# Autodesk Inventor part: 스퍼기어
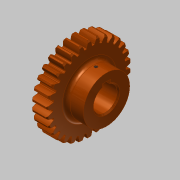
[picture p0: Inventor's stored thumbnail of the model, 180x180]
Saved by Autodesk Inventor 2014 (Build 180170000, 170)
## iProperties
Created: 2019-01
Part Number: 스퍼기어
Material: 알루미늄 6061
Document SubType Name: Modeling
Designer: mduedu
Density: 1 g/cm^3
Appearance: 매끄러움 - 연한 주황색
Author: mduedu
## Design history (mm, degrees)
sketch "스케치1"
  geometry: C1 r 27.5 at (0, 0); 1 further point
  constraints: 1 centre point, 1 coincident
  dimensions: "d0" = 55 diameter of C1
extrude "돌출1" new body sketch "스케치1" stored distance "d2" = 12; taper "d3" = 0 deg
sketch "스케치2" dims "d4" = 60
  geometry: L1 (0, 0)-(-32, 0); L2 (0, 0)-(0, 32); L3 (-0.57, 0)-(-0.57, 31.995); L4 (-1.57, 0)-(-1.57, 31.961); L5 (-2.07, 0)-(-2.07, 31.933); C1 r 27.5 at (0, 0); A1 r 32 centre (0, 0) between (-32, 0) and (0, 32); A2 r 9.292 centre (7.208, 26.911) between (-0.57, 31.995) and (-2.07, 27.422); A3 r 9.292 centre (-7.208, 26.911) between (2.07, 27.422) and (0.57, 31.995); A4 r 27.5 centre (0, 0) between (2.07, 27.422) and (-2.07, 27.422); A5 r 32 centre (0, 0) between (0.57, 31.995) and (-0.57, 31.995); 3 further points
  constraints: 14 point on circle, 10 end point, 6 centre point, 5 coincident, 5 point on line, 3 symmetric about line, 2 parallel, 2 perpendicular, 1 horizontal, 7 other
  dimensions: "d6" = 64 diameter of A1; "d7" = 0.5 distance between parallel lines of L4 L5; "d8" = 1 distance between parallel lines of L3 L4; "d9" = 1.57 distance between parallel lines of L2 L4
extrude "돌출2" join sketch "스케치2" stored distance "d10" = 0; taper "d11" = 0 deg
chamfer "모따기1" distance "d12" = 1; stored, may be unused: second distance "d13" = 2, angle "d14" = 45 deg
fillet "모깎기1" dims "d15" = 0.5
sketch "스케치3"
  geometry: C1 r 17.5 at (0, 0); 1 further point
  constraints: 1 centre point, 1 coincident
  dimensions: "d19" = 35 diameter of C1
extrude "돌출3" join sketch "스케치3" distance "d20" = 13; taper "d21" = 0 deg
sketch "스케치4"
  geometry: L1 (-3, 8.485)-(3, 8.485); L2 (3, 8.485)-(3, 11.8); L3 (3, 11.8)-(-3, 11.8); L4 (-3, 11.8)-(-3, 8.485); A1 r 9 centre (0, 0) between (-3, 8.485) and (3, 8.485); 1 further point
  constraints: 8 end point, 2 parallel, 2 point on circle, 1 centre point, 1 coincident, 1 horizontal, 1 perpendicular
  dimensions: "d22" = 18 diameter of A1; "d23" = 6 distance of L2.end L3.end; "d24" = 20.8 dimension on A1 L3
extrude "돌출4" cut sketch "스케치4" stored distance "d25" = 13; taper "d26" = 0 deg
sketch "스케치5"
  geometry: C1 r 15 at (0, 0); C2 r 22.5 at (0, 0); 1 further point
  constraints: 2 centre point, 2 coincident
  dimensions: "d33" = 30 diameter of C1; "d34" = 45 diameter of C2
extrude "돌출5" cut sketch "스케치5" distance "d30" = 6; taper "d31" = 0 deg
fillet "모깎기2" dims "d32" = 3
node "작업 평면1"
sketch "스케치6"
  geometry: L1 (17.5, 13)-(-17.5, 13) reference; 2 further points
  constraints: 1 vertical alignment
  dimensions: "d35" = 8 distance from line of point (0, 5) L1
hole "구멍1" sketch "스케치6" at (0, 5) diameter "d36" = 2.459; stored, may be unused: countersink angle "d40" = 90 deg, drill point angle "d42" = 118 deg; dims "d37" = 6, "d38" = 4, "d39" = 2, "d41" = 8
fillet "모깎기3" dims "d43" = 3
chamfer "모따기2" distance "d44" = 1; stored, may be unused: second distance "d45" = 2, angle "d46" = 45 deg
node "솔리드1"
pattern_circular "원형 패턴1" dims "d17" = 360 deg
